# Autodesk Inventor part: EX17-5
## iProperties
Shininess: 64.0
Length Units: 11272
Angle Units: 11279
Time Units: 11290
Mass Units: 11286
Length Display Precision: 3
Compacted: True
Part Number: EX17-5
Document SubType Name: Modeling
Created: 2002-11
Designer: E. MOSS
Project: EVERGREEN VALLEY COLLEGE
Description: PIN, 0.5 DIA X 1.35L
Authority: MS.TEACHER
Density: 0.0
Volumn: 0.0
Area: 0.0
PropertySet Name: Model Information
Control State: 0
Master: False
Checked Out: False
Author: E. MOSS
Revision Number: A
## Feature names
1. Extrusion1
